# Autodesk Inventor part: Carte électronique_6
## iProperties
Created: 2010-07
Part Number: Carte électronique_6
Document SubType Name: Modeling
Designer: eric
Density: 1 g/cm^3
Author: eric
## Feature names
1. Base1
